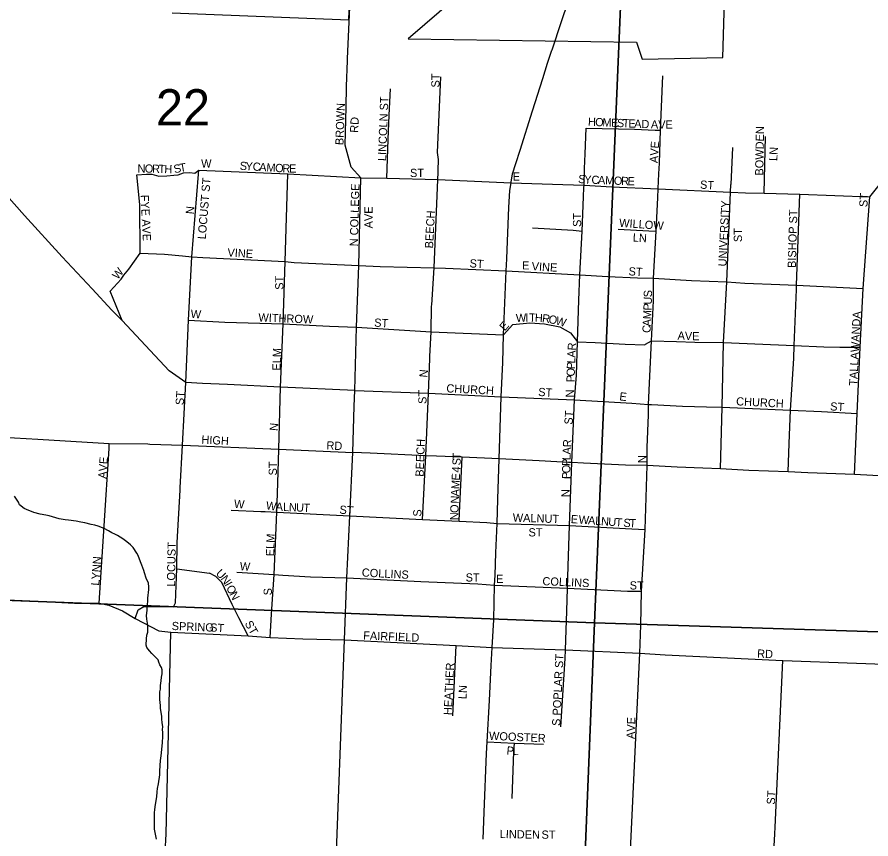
# Model space of a CAD drawing. Extents: x 1310247 to 1552180, y 377264 to 706493.
# Drawn here: x 1332965 to 1338164, y 555687 to 560693 of the extents above; entities that cross this region are included whole.
import ezdxf

# ---------------------------------------------------------------- set-up
doc = ezdxf.new("R2010")
doc.units = 0
for name, color, linetype in [('GM_X_City_Street', 7, 'Continuous'), ('GM_X_City_Street_Text', 7, 'Continuous'), ('GM_X_Corporation', 7, 'Continuous'), ('GM_X_County_Road', 7, 'Continuous'), ('GM_X_Minor_River', 7, 'Continuous'), ('GM_X_Section', 7, 'Continuous'), ('GM_X_Section_Text', 7, 'Continuous'), ('GM_X_State_Route', 7, 'Continuous'), ('GM_X_US_Route', 7, 'Continuous')]:
    doc.layers.add(name, color=color, linetype=linetype)

msp = doc.modelspace()

# ---------------------------------------------------------------- linework, layer by layer
at = {"layer": 'GM_X_City_Street'}
for points in [[(1338157.4, 559597.6), (1338384.9, 559881.4), (1338455.9, 559983.6), (1338550.9, 560084), (1338628.2, 560147.9), (1338722.7, 560215.9), (1338781, 560264.5), (1338820.7, 560307.8), (1338930.3, 560467.7), (1338958.4, 560502.4)], [(1336868.7, 559649.5), (1336873.1, 559737.2), (1336875.7, 559802.1), (1336883.5, 560004.5), (1336897.5, 560335.7)], [(1335528, 559746.9), (1335528.1, 559757.8), (1335531.6, 559825.2), (1335524, 559868.3), (1335544.7, 560329.4)], [(1335058.8, 559714.4), (1334998.3, 559779.2), (1334963.2, 559912.5), (1334969.6, 560143.5), (1334970.6, 560267.9)], [(1335217.3, 559711), (1335225.1, 559947.4), (1335230.5, 560094.4), (1335237.7, 560254.9)], [(1336416.5, 559654.5), (1336417.3, 559667.9), (1336419.2, 559771), (1336424.5, 559859.1), (1336430.7, 560016.5)], [(1336430.7, 560016.5), (1336723.5, 560009.5), (1336850.6, 560004.3), (1336883.5, 560004.5)], [(1337513.8, 559620.4), (1337521.7, 559964.4)], [(1337311.9, 559673.8), (1337322.3, 559897.4)], [(1333693.6, 559731.2), (1333752.1, 559736.2), (1333785.2, 559736.3), (1333827.5, 559724.6), (1333877.5, 559725.2), (1333918.7, 559729.1), (1333946.1, 559731.5), (1333979, 559744.2), (1334017.8, 559746.8), (1334047.6, 559741), (1334071.3, 559759.9)], [(1333991.8, 558466), (1334008.4, 558846.7), (1334029.9, 559232.8), (1334069.3, 559734.9), (1334069.4, 559735.3), (1334071.3, 559759.9)], [(1334071.3, 559759.9), (1334613.9, 559737.4), (1335058.8, 559714.4), (1335217.3, 559711), (1335527.3, 559702.9), (1335973.4, 559683.7)], [(1333714.1, 559255.4), (1333713.3, 559551.3), (1333693.6, 559731.2)], [(1334558.1, 558060.8), (1334569, 558439.1), (1334585.3, 558823.8), (1334596.3, 559203.1), (1334613.9, 559737.4)], [(1335020.5, 558417.4), (1335030.9, 558803.7), (1335045.4, 559180), (1335058.8, 559714.4)], [(1335489.4, 558939.7), (1335503.9, 559165.2), (1335527.3, 559702.9), (1335528, 559746.9)], [(1335973.4, 559683.7), (1336288, 559672.5), (1336417.3, 559667.9), (1336586.9, 559658.7), (1336868.6, 559647.3), (1337309.7, 559626.9), (1337400.5, 559622.2), (1337513.8, 559620.4), (1337730.2, 559613.7), (1338157.4, 559597.6)], [(1337247.2, 557940.6), (1337257.3, 558317.1), (1337267.2, 558711.1), (1337287, 559079.8), (1337309.7, 559626.9), (1337311.8, 559672.3), (1337311.9, 559673.8)], [(1336358.6, 558361.8), (1336370.3, 558510.7), (1336376.4, 558713.8), (1336384.5, 558968.1), (1336390.9, 559123.7), (1336404.9, 559388.8), (1336413.1, 559597.2), (1336416.5, 559654.5)], [(1336800.7, 557960.7), (1336802.4, 558070.9), (1336810.4, 558270.5), (1336810.4, 558333.6), (1336827.5, 558721.6), (1336839.1, 558964.8), (1336840, 559101.9), (1336855.7, 559388.9), (1336866.5, 559593), (1336868.6, 559647.3), (1336868.7, 559649.5)], [(1337659.6, 557922.7), (1337665.3, 558095), (1337674.8, 558298.4), (1337695.2, 558613.4), (1337697.3, 558691.8), (1337709.9, 559032.4), (1337710.9, 559060), (1337730.2, 559613.7)], [(1338063.2, 557906.2), (1338080.6, 558279), (1338099.3, 558681.6), (1338115.9, 559040.1), (1338157.4, 559597.6)], [(1336103.8, 559408.7), (1336350.1, 559394.4), (1336404.9, 559388.8)], [(1336625.6, 559399.9), (1336812.3, 559390.6), (1336855.7, 559388.9)], [(1333615.8, 559119.7), (1333645.1, 559158.2), (1333714.1, 559255.4), (1333862.2, 559247.7), (1333972.5, 559237.9)], [(1333972.5, 559237.9), (1334029.9, 559232.8), (1334096.8, 559229.2), (1334596.3, 559203.1), (1334651.6, 559198.8), (1335045.4, 559180), (1335175.7, 559173.5), (1335503.9, 559165.2), (1335574.2, 559162.4), (1335943.1, 559146.8)], [(1335943.1, 559146.8), (1336390.9, 559123.7), (1336562.6, 559112.5), (1336742.3, 559103.5), (1336840, 559101.9), (1337071, 559088.5), (1337287, 559079.8), (1337395.6, 559072.8), (1337609.2, 559064.4), (1337710.9, 559060), (1338115.9, 559040.1)], [(1333604.8, 558845), (1333532.6, 559023.9), (1333598, 559096.3), (1333615.8, 559119.7)], [(1329305.9, 559062.5), (1329651.5, 558835.9), (1330083.1, 558553.2), (1330361.1, 558371.6), (1330455, 558329.7), (1330505.6, 558314.1), (1330656.4, 558296.8), (1331140.3, 558224.9), (1331451, 558197.5), (1332026.8, 558170.9), (1332734.3, 558142.5), (1333090.8, 558121.8), (1333525.7, 558095.8), (1333761.6, 558092.5)], [(1335478.3, 558625.6), (1335485.5, 558776.5), (1335488.9, 558932.5), (1335489.4, 558939.7)], [(1334008.4, 558846.7), (1334229.5, 558833.8), (1334585.3, 558823.8), (1334866.6, 558811.1), (1335030.9, 558803.7), (1335485.5, 558776.5), (1335927.3, 558758.2)], [(1335927.3, 558758.2), (1335982.8, 558821), (1336087.5, 558830.3), (1336176.1, 558823.6), (1336268.9, 558806.6), (1336333.9, 558769.9), (1336376.4, 558713.8), (1336485.4, 558710.5), (1336667.7, 558700.2), (1336787, 558697.4), (1336790.4, 558699.5)], [(1336790.4, 558699.5), (1336827.5, 558721.6), (1336980, 558716.1), (1337090.7, 558712.7), (1337267.2, 558711.1), (1337697.3, 558691.8), (1337877.8, 558684.4), (1337973.6, 558682.7), (1338099.3, 558681.6)], [(1335469.1, 558401.3), (1335477.6, 558611), (1335478.3, 558625.6)], [(1333957.3, 557811.7), (1333958.1, 557826), (1333972, 558085.4), (1333991.8, 558466)], [(1335020.5, 558417.4), (1335469.1, 558401.3), (1335912.1, 558379.3), (1336358.6, 558361.8)], [(1335432.8, 557632), (1335452.8, 558021), (1335469.1, 558401.3)], [(1336328.3, 557596.6), (1336343.1, 557979.4), (1336358.6, 558361.8)], [(1336358.6, 558361.8), (1336707.4, 558341), (1336810.4, 558333.6), (1336827.9, 558332.7)], [(1336827.9, 558332.7), (1337015.7, 558322.2), (1337161.8, 558319.4), (1337257.3, 558317.1), (1337674.8, 558298.4), (1337862.4, 558289.8), (1338080.6, 558279)], [(1333464.7, 557123.3), (1333525.1, 558064.9), (1333525.7, 558095.8)], [(1333761.6, 558092.5), (1333773.4, 558092.4), (1333972, 558085.4)], [(1333972, 558085.4), (1334558.1, 558060.8), (1335009.6, 558040.8)], [(1334505.3, 556914.3), (1334514.8, 557055.4), (1334531.2, 557297.4), (1334546.1, 557676.5), (1334550.4, 557792.7), (1334554.7, 557921.6), (1334558.1, 558060.8)], [(1334959, 556898.7), (1334973.5, 557277.8), (1334990.9, 557654.4), (1335009.6, 558040.8)], [(1335657.2, 557622), (1335659.5, 557673.7), (1335674.1, 558011.5)], [(1336755.9, 556818.8), (1336762.2, 556988.5), (1336767.1, 557195.4), (1336790.1, 557571.6), (1336800.7, 557960.7)], [(1333934.1, 557230.2), (1333938, 557332.5), (1333940.2, 557493.4), (1333957.3, 557811.7)], [(1334267.8, 557688.5), (1334448.6, 557681.8)], [(1334448.6, 557681.8), (1334475.3, 557680.8), (1334546.1, 557676.5), (1334990.9, 557654.4)], [(1334990.9, 557654.4), (1335432.8, 557632), (1335657.2, 557622), (1335825.3, 557613.5), (1335888.1, 557608.2), (1336328.3, 557596.6)], [(1336301.7, 556786.4), (1336304.9, 556838.4), (1336308.4, 556957.6), (1336312, 557074), (1336316.6, 557213.9), (1336319.9, 557347.6), (1336328.3, 557596.6)], [(1336328.3, 557596.6), (1336708.7, 557576), (1336790.1, 557571.6)], [(1333938, 557332.5), (1334136.7, 557305.1)], [(1329511.2, 557288.5), (1330122.9, 557253.6), (1330428.4, 557249.1), (1331035.9, 557226.6), (1332153.7, 557169.2), (1332761.8, 557149.4), (1333043.6, 557136.3), (1333314.8, 557124), (1333464.7, 557123.3), (1333524.5, 557111.3), (1333606.5, 557077.1), (1333683.7, 557029.5), (1333828.5, 556954.2), (1333901, 556947.3)], [(1334371.5, 556924.3), (1334314.3, 557033.6), (1334274.2, 557115.6), (1334211, 557248.8), (1334175.1, 557284.6), (1334136.7, 557305.1)], [(1334302.4, 557311.1), (1334531.2, 557297.4), (1334582.7, 557294.2)], [(1334582.7, 557294.2), (1334751.5, 557283.8), (1334973.5, 557277.8), (1335422.7, 557254), (1335770.3, 557240.6), (1335872.6, 557233.3)], [(1333794.2, 557101.9), (1333916.4, 557100.2), (1333930.1, 557125), (1333934.1, 557230.2)], [(1335872.6, 557233.3), (1336316.6, 557213.9), (1336682.3, 557196.1), (1336767.1, 557195.4)], [(1333683.7, 557029.5), (1333702.9, 557083.1), (1333736.2, 557102.8), (1333794.2, 557101.9)], [(1333853.3, 554038), (1333806, 554146.4), (1333800.1, 554276.2), (1333805.2, 554466.6), (1333873.4, 555718.6), (1333901, 556947.3)], [(1333901, 556947.3), (1334371.5, 556924.3), (1334505.3, 556914.3), (1334505.3, 556914.3)], [(1334505.3, 556914.3), (1334704.5, 556905.5), (1334959, 556898.7), (1335638.5, 556864.3), (1335858.3, 556853.7)], [(1334869.7, 554428.6), (1334888.2, 554890), (1334890.2, 555064.3), (1334891.5, 555126.5), (1334959, 556898.7)], [(1335618.9, 556436.2), (1335638.5, 556864.3)], [(1335858.3, 556853.7), (1335858.3, 556853.7), (1336304.9, 556838.4), (1336755.9, 556818.8), (1336910.9, 556809), (1337628.2, 556774), (1338523.8, 556740.8), (1338639.8, 556737.7), (1339104.2, 556723.8), (1339180.2, 556718.9)], [(1336676.1, 555103.4), (1336755.9, 556818.8)], [(1336275.5, 556370.2), (1336301.7, 556786.4)], [(1337580.1, 555758.3), (1337628.2, 556774)], [(1335827.1, 556277.6), (1335993.2, 556271.2), (1336170.6, 556263.6)], [(1335980.1, 555933.9), (1335990.3, 556218.9), (1335993.2, 556271.2)], [(1337500.6, 554315.7), (1337508.5, 554422.4), (1337578.2, 555718), (1337580.1, 555758.3)]]:
    msp.add_lwpolyline(points, dxfattribs=at)
at = {"layer": 'GM_X_Corporation'}
for points in [[(1335636.3, 560811.3), (1335346.5, 560560.8), (1336737.3, 560538.9), (1336771.2, 560436.4), (1337261.7, 560445.6), (1337273.5, 560861.1)], [(1333908.5, 560718.1), (1334984.1, 560675.6), (1334990.3, 560838.9)]]:
    msp.add_lwpolyline(points, dxfattribs=at)
at = {"layer": 'GM_X_County_Road'}
for points in [[(1334976, 560426.6), (1334976.5, 560440.4), (1334992.5, 560796.6)], [(1334970.6, 560267.9), (1334970.7, 560271.6), (1334976, 560426.6)]]:
    msp.add_lwpolyline(points, dxfattribs=at)
at = {"layer": 'GM_X_Minor_River'}
for points in [[(1333843, 556650.9), (1333843.8, 556673), (1333848.5, 556693), (1333849.3, 556717.1), (1333843.7, 556731.4), (1333834.2, 556747.8), (1333828.7, 556764.1), (1333823.1, 556778.4), (1333786.1, 556815.8), (1333770.6, 556832.5), (1333755.1, 556853.1), (1333751.6, 556867.3), (1333752.9, 556905.5), (1333755.6, 556927.5), (1333760.2, 556945.5), (1333760.9, 556965.6), (1333761.7, 556987.7), (1333760.1, 557001.8), (1333754.9, 557026.1), (1333753.6, 557048.3), (1333756.6, 557078.4), (1333757.2, 557094.4), (1333760.5, 557134.5), (1333761.1, 557152.6), (1333767, 557206.8), (1333767.5, 557222.8), (1333764.2, 557245.1), (1333751.1, 557275.7), (1333740.1, 557308.2), (1333736.6, 557322.5), (1333723.6, 557355.1), (1333716.2, 557375.5), (1333701.4, 557414.2), (1333693.8, 557428.5), (1333672.7, 557461.4), (1333655.2, 557478.1), (1333633.7, 557497), (1333608, 557514), (1333576.5, 557535.2), (1333560.7, 557543.8), (1333542.8, 557550.4), (1333521.1, 557563.2), (1333495.4, 557578.2), (1333459.6, 557591.5), (1333437.7, 557598.3), (1333415.7, 557603.1), (1333377.7, 557612.4), (1333353.7, 557617.3), (1333325.7, 557622.2), (1333277.5, 557627.9), (1333257.5, 557630.6), (1333221.4, 557635.9), (1333159.6, 557654.1), (1333139.6, 557658.8), (1333105.6, 557666), (1333067.7, 557675.4), (1333021.9, 557693.1), (1333008, 557699.6), (1332980.6, 557722.7), (1332973.1, 557739), (1332950.1, 557774)], [(1333814.8, 555686.3), (1333809.5, 555706.6), (1333800.8, 555747.2), (1333801.4, 555767.3), (1333801.1, 555817.6), (1333802.1, 555845.7), (1333804.7, 555865.7), (1333807.8, 555895.8), (1333815.4, 555943.8), (1333818.4, 555973.9), (1333819.1, 555994), (1333826.1, 556021.9), (1333834, 556077.9), (1333834.8, 556102), (1333838.9, 556164.3), (1333841.8, 556192.3), (1333844.5, 556212.3), (1333847.9, 556254.5), (1333850.5, 556272.5), (1333851.9, 556312.7), (1333852.6, 556334.8), (1333851.2, 556352.9), (1333851.8, 556369), (1333848.6, 556395.3), (1333847.3, 556417.4), (1333845.9, 556435.6), (1333841, 556470), (1333837.5, 556484.2), (1333838, 556500.2), (1333833.2, 556536.6), (1333834.7, 556582.8), (1333837.3, 556598.8), (1333838, 556620.9), (1333843, 556650.9)]]:
    msp.add_lwpolyline(points, dxfattribs=at)
at = {"layer": 'GM_X_Section'}
for points in [[(1331440.5, 562542.2), (1336706.8, 562346.4), (1336481.3, 557003), (1331237.8, 557204.3)], [(1341986.1, 562118.5), (1341788.1, 556834.5), (1336481.3, 557003), (1336706.8, 562346.4)], [(1331237.8, 557204.3), (1336481.3, 557003), (1336267.4, 551747.3), (1331016.4, 551943.3)], [(1336481.3, 557003), (1341788.1, 556834.5), (1341571.6, 551554.6), (1336267.4, 551747.3)]]:
    msp.add_lwpolyline(points, close=True, dxfattribs=at)
at = {"layer": 'GM_X_State_Route'}
for points in [[(1336222, 560492.2), (1336278.9, 560665.4), (1336320, 560785.9), (1336362, 560878), (1336403.2, 560946.7), (1336424.5, 560976.1)], [(1335973.9, 559686.5), (1335982, 559737.7), (1336002, 559800.5), (1336028.2, 559882.7), (1336103.2, 560121.6), (1336166.7, 560319.1), (1336195, 560412.7), (1336221.6, 560490.7), (1336222, 560492.2)], [(1335900.2, 558001.4), (1335912.1, 558379.3), (1335922.2, 558588.5), (1335927.3, 558758.2), (1335943.1, 559146.8), (1335946.5, 559220.5), (1335951, 559328.7), (1335959.4, 559533), (1335965.4, 559636.2), (1335973.4, 559683.7), (1335973.9, 559686.5)], [(1335803.2, 555686.6), (1335808.3, 555849.6), (1335822.8, 556206.7), (1335827.1, 556277.6), (1335840.8, 556530.1), (1335852.2, 556743.8), (1335858.3, 556853.7), (1335868, 557021.9), (1335872.6, 557233.3), (1335876.2, 557293.9), (1335879, 557429.9), (1335888.1, 557608.2), (1335891.2, 557757.2), (1335900.2, 558001.4)]]:
    msp.add_lwpolyline(points, dxfattribs=at)
at = {"layer": 'GM_X_US_Route'}
for points in [[(1333991.8, 558466), (1333892, 558538.1), (1333775.3, 558661.6), (1333604.8, 558845), (1333542.2, 558908.1), (1333421.5, 559038.2), (1333239.7, 559232.3), (1333011, 559483.1), (1332851.8, 559661.6), (1332681.9, 559873.8), (1332613.9, 559954.6), (1332508.5, 560090.5), (1332359.2, 560273.4), (1332129.1, 560553.2), (1331971.9, 560751.3), (1331839.4, 560916.8), (1331762.5, 561017.8), (1331595.5, 561220.8), (1331494, 561345), (1331326, 561554.9), (1331199.9, 561712.6), (1331138, 561788.6)], [(1334094.6, 558461.3), (1333991.8, 558466)], [(1335020.5, 558417.4), (1334569, 558439.1), (1334245.8, 558454.3), (1334094.6, 558461.3)], [(1335009.6, 558040.8), (1335018.1, 558322), (1335020.5, 558417.4)], [(1335114.4, 558036.1), (1335009.6, 558040.8)], [(1335900.2, 558001.4), (1335674.1, 558011.5), (1335518.3, 558017.4), (1335452.8, 558021), (1335114.4, 558036.1)], [(1336322.7, 557980.5), (1336143, 557990.5), (1335900.2, 558001.4)], [(1339223.2, 557859), (1339223.5, 557863.9), (1338869.9, 557872.9), (1338494.2, 557888.4), (1338175.7, 557899.8), (1338063.2, 557906.2), (1337780.4, 557917.8), (1337659.6, 557922.7), (1337419.5, 557930.8), (1337247.2, 557940.6), (1337141, 557945.5), (1336984.2, 557950.5), (1336800.7, 557960.7), (1336669.8, 557964.3), (1336414.2, 557974.9), (1336343.1, 557979.4), (1336322.7, 557980.5)]]:
    msp.add_lwpolyline(points, dxfattribs=at)

# ---------------------------------------------------------------- texts
at = {"layer": 'GM_X_City_Street_Text'}
for s, rotation, p in [('ST', 90, (1335537.1, 560263.6)), ('LINCOLN ST', 87.8784, (1335211.5, 559815)), ('BROWN', 87.839, (1334951.9, 559911.9)), ('RD', 86.9876, (1335041.3, 559986.8)), ('H', 357.5513, (1336440.1, 560031)), ('O', 357.5513, (1336484.1, 560029.1)), ('M', 357.5404, (1336528, 560027.2)), ('E', 357.5404, (1336580.8, 560025)), ('S', 357.551, (1336616, 560023.4)), ('T', 357.5404, (1336651.1, 560022)), ('E', 357.5404, (1336686.3, 560020.4)), ('A', 357.5426, (1336721.5, 560018.9)), ('D', 357.5513, (1336765.4, 560017.1)), ('A', 358.5572, (1336823.6, 560014.6)), ('V', 359.9519, (1336868.9, 560013.4)), ('E', 359.9939, (1336912.9, 560013.4)), ('BOWDEN', 89.0608, (1337508.3, 559726.9)), ('AVE', 86.186, (1336865.9, 559802.2)), ('LN', 86.987, (1337593.3, 559815.2)), ('W', 0, (1334085.7, 559775.8)), ('S', 356.6103, (1334319.5, 559762.6)), ('N', 359.9781, (1333698.5, 559745)), ('O', 359.6721, (1333742.4, 559745)), ('R', 358.3484, (1333786.1, 559744.7)), ('T', 357.9779, (1333825.6, 559743.6)), ('H', 357.945, (1333860.8, 559742.3)), ('S', 13.7935, (1333925, 559740.3)), ('T', 10.0238, (1333958.3, 559748.5)), ('Y', 356.5885, (1334354.6, 559760.5)), ('C', 356.6306, (1334398.6, 559757.9)), ('A', 356.5885, (1334438.1, 559755.5)), ('M', 356.6185, (1334482, 559752.9)), ('O', 356.6103, (1334534.8, 559749.8)), ('R', 357.4788, (1334579.5, 559747.2)), ('E', 359.4427, (1334620.9, 559745.3)), ('ST', 0, (1335357.3, 559718.6)), ('LOCUST ST', 85.3646, (1334113.7, 559337.8)), ('E', 0, (1335982.1, 559696.6)), ('S', 354.4179, (1336379.3, 559683.3)), ('Y', 356.9219, (1336416.7, 559679.7)), ('C', 357.7947, (1336461.5, 559677.3)), ('A', 357.8085, (1336501.1, 559675.8)), ('M', 357.7956, (1336545, 559674.1)), ('O', 357.7919, (1336597.8, 559672.1)), ('R', 357.7895, (1336641.8, 559670.4)), ('E', 357.806, (1336681.4, 559668.9)), ('N COLLEGE', 88.5123, (1335039.9, 559295.8)), ('ST', 356.4257, (1337122.3, 559648.2)), ('FYE AVE', 272.9626, (1333716.7, 559609)), ('ST', 86.186, (1338141.9, 559533.8)), ('UNIVERSITY', 87.2408, (1337283.9, 559172.8)), ('N', 84.2889, (1334041.1, 559490.1)), ('AVE', 90, (1335130.3, 559405.6)), ('BEECH', 86.9337, (1335497.5, 559282.9)), ('BISHOP ST', 88.3398, (1337706.3, 559163.9)), ('ST', 90, (1336399.5, 559414.4)), ('WILLOW', 356.0502, (1336629.6, 559415)), ('ST', 90, (1337378.7, 559322)), ('LN', 356.9889, (1336712.9, 559325.6)), ('VINE', 356.5337, (1334244.7, 559234.6)), ('ST', 356.4256, (1335718.7, 559168.6)), ('E', 0, (1336039.3, 559155.4)), ('VINE', 356.5337, (1336097.1, 559151)), ('W', 49.8834, (1333577.2, 559090.8)), ('ST', 356.4257, (1336686.7, 559120.2)), ('ST', 90, (1334586.7, 559031.6)), ('U', 88.5248, (1336829.5, 558940.5)), ('S', 89.9294, (1336830.6, 558985.8)), ('P', 87.4719, (1336827.9, 558904.3)), ('W', 355.6037, (1334020.4, 558860.5)), ('WITHROW', 357.8288, (1334433.5, 558838.6)), ('W', 2.9098, (1336003.6, 558834.2)), ('I', 1.8363, (1336060.5, 558837.1)), ('T', 358.8525, (1336081.8, 558837.8)), ('H', 357.0043, (1336116.5, 558837.1)), ('R', 352.7191, (1336159.5, 558834.9)), ('O', 349.2489, (1336198, 558830)), ('M', 87.4745, (1336825.6, 558851.5)), ('TALLAWANDA', 87.1083, (1338080.3, 558446.6)), ('ST', 356.4256, (1335137.9, 558807.8)), ('E', 50.1989, (1335935.3, 558778)), ('W', 344.4253, (1336240.1, 558822)), ('A', 87.4721, (1336823.6, 558807.6)), ('C', 87.4735, (1336821.9, 558768)), ('A', 357.6826, (1336985.7, 558728.6)), ('V', 357.6988, (1337029.7, 558726.8)), ('E', 358.6948, (1337074.6, 558725)), ('ELM', 88.5312, (1334569.1, 558539)), ('R', 87.3371, (1336366.8, 558661.2)), ('L', 87.3354, (1336363.1, 558582.1)), ('A', 87.3384, (1336364.8, 558617.3)), ('P', 87.3695, (1336361.5, 558546.9)), ('N', 84.2883, (1335462.4, 558495.7)), ('O', 88.1254, (1336360.1, 558503.1)), ('P', 89.6892, (1336359.9, 558468.3)), ('ST', 86.4237, (1333979.5, 558328.2)), ('ST', 90, (1335457.9, 558336.4)), ('CHURCH', 357.0407, (1335577.8, 558407.4)), ('ST', 356.4257, (1336136.7, 558385.4)), ('N', 90, (1336355.5, 558376)), ('E', 352.8792, (1336630.1, 558358.9)), ('CHURCH', 357.0407, (1337342.2, 558328.2)), ('ST', 356.4256, (1337914.3, 558297.4)), ('ST', 86.4237, (1336346.7, 558209.4)), ('N', 84.2889, (1334551.6, 558170.1)), ('HIGH', 356.7313, (1334086.2, 558095)), ('RD', 356.9889, (1334847.4, 558059.8)), ('BEECH', 87.9549, (1335440.3, 557892.3)), ('R', 87.1353, (1336338.1, 558071.6)), ('A', 87.1381, (1336335.9, 558027.7)), ('AVE', 86.055, (1333508.7, 557879.4)), ('S', 87.3707, (1335664.8, 557961.5)), ('T', 87.3721, (1335666.4, 557996.7)), ('P', 88.8219, (1336333.6, 557957.7)), ('L', 87.3832, (1336334.3, 557992.6)), ('N', 90, (1336795.5, 557975.6)), ('ST', 90, (1334547.1, 557900.8)), ('4', 87.37, (1335662.8, 557917.5)), ('O', 89.959, (1336333.5, 557914)), ('E', 87.3707, (1335660.6, 557869.2)), ('P', 89.9556, (1336333.5, 557878.8)), ('M', 87.368, (1335658.1, 557816.4)), ('A', 87.3624, (1335656.1, 557772.5)), ('N', 90, (1336329.1, 557768.8)), ('W', 355.6037, (1334284.4, 557703.4)), ('W', 353.1409, (1334478.5, 557694.5)), ('A', 356.2969, (1334538.3, 557687.4)), ('L', 357.8147, (1334583.7, 557684.5)), ('N', 357.8803, (1334618.9, 557683.2)), ('N', 87.3657, (1335654.1, 557728.5)), ('U', 357.8794, (1334662.9, 557681.5)), ('T', 357.8685, (1334706.9, 557679.9)), ('ST', 356.188, (1334926.7, 557668.2)), ('S', 90, (1335427.1, 557650)), ('O', 87.8306, (1335651.8, 557671.5)), ('N', 89.5628, (1335651.5, 557627.9)), ('WALNUT', 358.0919, (1335982.4, 557619.8)), ('E', 356.0081, (1336334.8, 557611)), ('W', 356.0122, (1336383.1, 557607.6)), ('A', 356.0138, (1336440.1, 557603.7)), ('L', 356.0081, (1336484, 557600.6)), ('N', 356.0153, (1336519.2, 557598.2)), ('U', 356.0189, (1336563.1, 557595.1)), ('T', 356.0081, (1336606.9, 557592)), ('S', 356.0081, (1336655.2, 557588.7)), ('T', 357.8147, (1336692.1, 557586.1)), ('ST', 0, (1336078.9, 557529.4)), ('ELM', 88.0252, (1334529.5, 557408.3)), ('LOCUST', 88.9582, (1333926.7, 557223)), ('LYNN', 85.6006, (1333464.7, 557228.3)), ('W', 355.587, (1334319.6, 557325)), ('U', 314.5537, (1334171.5, 557300.3)), ('COLLINS', 357.0908, (1335063, 557285.4)), ('N', 306.0195, (1334201.1, 557270.5)), ('ST', 0, (1335696.1, 557254.6)), ('E', 0, (1335880.9, 557245.8)), ('COLLINS', 357.5087, (1336162.9, 557232.6)), ('I', 298.1882, (1334226, 557236.4)), ('O', 297.4155, (1334236.3, 557217.2)), ('ST', 0, (1336694.9, 557206.2)), ('N', 297.4131, (1334256.6, 557178.1)), ('S', 90, (1334516.3, 557170.4)), ('SPRING', 357.6595, (1333905.7, 556959.8)), ('ST', 299.7461, (1334349.1, 556999.1)), ('ST', 356.4257, (1334139.1, 556951)), ('FAIRFIELD', 357.5787, (1335071.7, 556902)), ('S POPLAR ST', 87.2735, (1336271.9, 556374.4)), ('RD', 356.9889, (1337469.8, 556792)), ('HEATHER', 87.3576, (1335612.1, 556440.4)), ('LN', 86.9876, (1335701.3, 556537.2)), ('AVE', 88.0252, (1336725.1, 556295.1)), ('WOOSTER', 357.4331, (1335837.6, 556291)), ('P', 354.6921, (1335943.8, 556201.9)), ('L', 358.0369, (1335982, 556198.4)), ('ST', 86.4237, (1337578.7, 555895)), ('LINDEN', 358.8989, (1335903.1, 555692.6)), ('ST', 0, (1336158.1, 555688.2))]:
    msp.add_text(s, height=50, rotation=rotation, dxfattribs=at).set_placement(p)
at = {"layer": 'GM_X_Section_Text'}
msp.add_text('22', height=221, rotation=0, dxfattribs=at).set_placement((1333810.7, 560032.3))

doc.saveas('drawing.dxf')
